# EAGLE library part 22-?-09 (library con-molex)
CONNECTOR wire to board 2.54 mm (.1 inch) pitch header
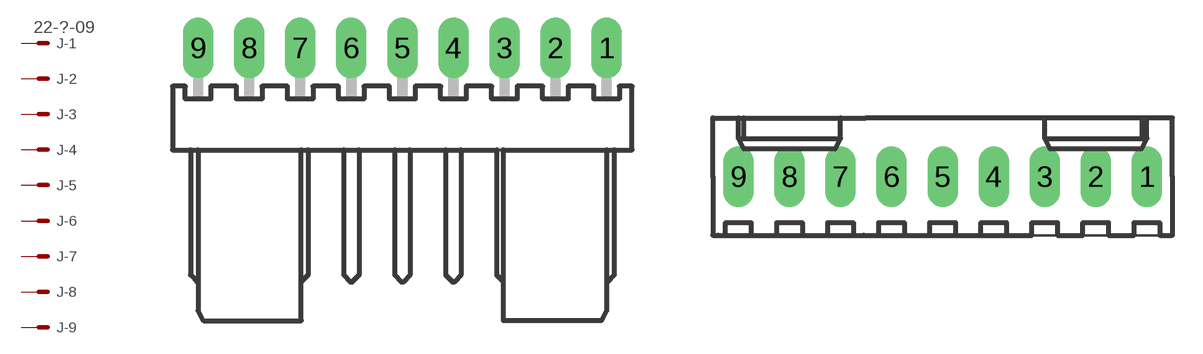
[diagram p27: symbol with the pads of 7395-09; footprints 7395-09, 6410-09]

Designator prefix J; gates -1=MV -2=M -3=M -4=M -5=M -6=M -7=M -8=M -9=M

## 22-05-7098-09 (OC_FARNELL: unknown; OC_NEWARK: unknown)  [7395-09]
1  -1:S  pas
2  -2:S  pas
3  -3:S  pas
4  -4:S  pas
5  -5:S  pas
6  -6:S  pas
7  -7:S  pas
8  -8:S  pas
9  -9:S  pas

## 22-27-2091-09 (OC_FARNELL: unknown; OC_NEWARK: unknown)  [6410-09]
Pads as for 7395-09

## Footprint 7395-09 (pad centres in mm)
MOLEX 2.54mm KK RA CONNECTOR Fixed Orientation
drill 1.016 long: 1 10.16,0; 2 7.62,0; 3 5.08,0; 4 2.54,0; 5 0,0; 6 -2.54,0; 7 -5.08,0; 8 -7.62,0; 9 -10.16,0

## Footprint 6410-09 (pad centres in mm)
MOLEX 2.54mm KK CONNECTOR
drill 1.016 long: 1 10.16,0; 2 7.62,0; 3 5.08,0; 4 2.54,0; 5 0,0; 6 -2.54,0; 7 -5.08,0; 8 -7.62,0; 9 -10.16,0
